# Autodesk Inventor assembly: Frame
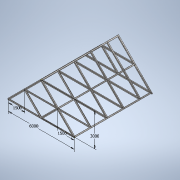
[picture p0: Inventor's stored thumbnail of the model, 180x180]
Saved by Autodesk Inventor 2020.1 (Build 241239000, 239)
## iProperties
_SolveAssemblyDoc: Frame Generator Solve Assembly
_Version: 15.0.0
Created: 2019-10
Part Number: Frame
Document SubType Name: Weldment
Designer: Synergysoft Dell02
Weld Material: Welded Aluminum-6061
Author: Synergysoft Dell02
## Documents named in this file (3)
- C:\Users\Synergysoft Dell02\Desktop\INV-01 Intro to Modeling_2020\FRAME\Frame.iam
- C:\Users\Synergysoft Dell02\Desktop\INV-01 Intro to Modeling_2020\FRAME\Frame.ipt
- C:\Users\Synergysoft Dell02\Desktop\INV-01 Intro to Modeling_2020\FRAME\Frame\Frame\Frame 1572343187933.iam
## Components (2 placed, 2 different names)
1. Frame:1
2. Frame 1572343187933:1 [sub-assembly]
